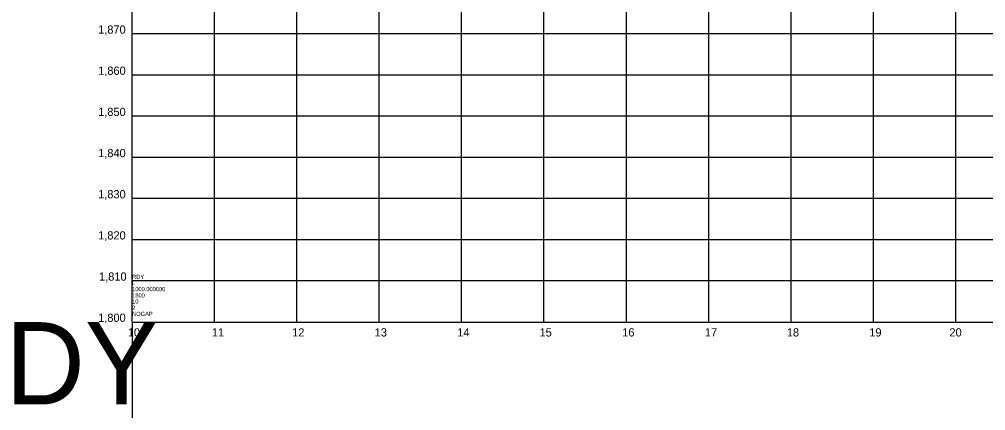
# Model space of a CAD drawing. Extents: x 553912 to 567693, y 512355 to 537539.
# Drawn here: x 557113 to 558286, y 513498 to 513973 of the extents above; entities that cross this region are included whole.
import ezdxf

# ---------------------------------------------------------------- set-up
doc = ezdxf.new("R2010")
doc.units = 0
for name, color, linetype in [('Exist Profile Cell', 7, 'Continuous'), ('Exist Vertical Profile Horizontal Axis Label Major', 7, 'Continuous'), ('Exist Vertical Profile Vertical Axis Label', 7, 'Continuous'), ('Sheet Profile Grid Major CELL', 7, 'Continuous')]:
    doc.layers.add(name, color=color, linetype=linetype)

msp = doc.modelspace()

# ---------------------------------------------------------------- linework, layer by layer
at = {"layer": 'Exist Profile Cell'}
for q in [(557249.5, 514855.4), (557249.5, 514855.4), (563849.5, 513605.4), (557249.5, 512355.4), (563849.5, 513605.4), (557249.5, 512355.4)]:
    msp.add_line((557249.5, 513605.4), q, dxfattribs=at)
at = {"layer": 'Sheet Profile Grid Major CELL'}
for p, q in [((557249.5, 513605.4), (557249.5, 514805.4)), ((557349.5, 513605.4), (557349.5, 514805.4)), ((557449.5, 513605.4), (557449.5, 514805.4)), ((557549.5, 513605.4), (557549.5, 514805.4)), ((557649.5, 513605.4), (557649.5, 514805.4)), ((557749.5, 513605.4), (557749.5, 514805.4)), ((557849.5, 513605.4), (557849.5, 514805.4)), ((557949.5, 513605.4), (557949.5, 514805.4)), ((558049.5, 513605.4), (558049.5, 514805.4)), ((558149.5, 513605.4), (558149.5, 514805.4)), ((558249.5, 513605.4), (558249.5, 514805.4)), ((563849.5, 513955.4), (557249.5, 513955.4)), ((563849.5, 513905.4), (557249.5, 513905.4)), ((563849.5, 513855.4), (557249.5, 513855.4)), ((563849.5, 513805.4), (557249.5, 513805.4)), ((563849.5, 513755.4), (557249.5, 513755.4)), ((563849.5, 513705.4), (557249.5, 513705.4)), ((563849.5, 513655.4), (557249.5, 513655.4))]:
    msp.add_line(p, q, dxfattribs=at)

# ---------------------------------------------------------------- texts
at = {"layer": 'Exist Profile Cell'}
for s, height, p in [('RDY', 5, (557249.5, 513657.9)), ('L', 5, (557249.5, 513650.4)), ('1000.000000', 5, (557249.5, 513642.9)), ('1800', 5, (557249.5, 513635.4)), ('2', 5, (557249.5, 513620.4)), ('10', 5, (557249.5, 513627.9)), ('NOGAP', 5, (557249.5, 513612.9)), ('RDY', 100, (556999, 513505.4))]:
    msp.add_text(s, height=height, dxfattribs=at).set_placement(p)
at = {"layer": 'Exist Vertical Profile Horizontal Axis Label Major'}
for s, p in [('10', (557244.2, 513587.9)), ('10', (557244.2, 513587.9)), ('11', (557346.3, 513587.9)), ('11', (557346.3, 513587.9)), ('12', (557443.8, 513587.9)), ('12', (557443.8, 513587.9)), ('13', (557543.9, 513587.9)), ('13', (557543.9, 513587.9)), ('14', (557644.2, 513587.9)), ('14', (557644.2, 513587.9)), ('15', (557744.1, 513587.9)), ('15', (557744.1, 513587.9)), ('16', (557844.5, 513587.9)), ('16', (557844.5, 513587.9)), ('17', (557944.8, 513587.9)), ('17', (557944.8, 513587.9)), ('18', (558044.3, 513587.9)), ('18', (558044.3, 513587.9)), ('19', (558144.4, 513587.9)), ('19', (558144.4, 513587.9)), ('20', (558241.7, 513587.9)), ('20', (558241.7, 513587.9))]:
    msp.add_text(s, height=10, dxfattribs=at).set_placement(p)
at = {"layer": 'Exist Vertical Profile Vertical Axis Label'}
for s, p in [('1,870', (557208.2, 513955.7)), ('1,870', (557208.2, 513955.7)), ('1,860', (557208.2, 513905.7)), ('1,860', (557208.2, 513905.7)), ('1,850', (557208.2, 513855.7)), ('1,850', (557208.2, 513855.7)), ('1,840', (557208.2, 513805.7)), ('1,840', (557208.2, 513805.7)), ('1,830', (557208.2, 513755.7)), ('1,830', (557208.2, 513755.7)), ('1,820', (557208.2, 513705.7)), ('1,820', (557208.2, 513705.7)), ('1,810', (557209.3, 513655.7)), ('1,810', (557209.3, 513655.7)), ('1,800', (557208.2, 513605.7)), ('1,800', (557208.2, 513605.7))]:
    msp.add_text(s, height=10, dxfattribs=at).set_placement(p)

doc.saveas('drawing.dxf')
